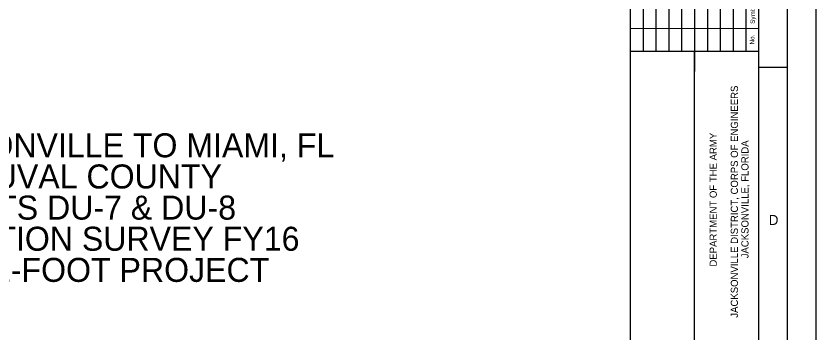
# Model space of a CAD drawing. Extents: x 464090 to 640095, y 2137521 to 2273520.
# Drawn here: x 584083 to 640089, y 2208273 to 2230445 of the extents above; entities that cross this region are included whole.
import ezdxf

# ---------------------------------------------------------------- set-up
doc = ezdxf.new("R2010")
doc.units = 0
for name, color, linetype in [('G-ANNO-NPLT', 7, 'Continuous'), ('G-ANNO-TEXT-TTLB', 7, 'Continuous'), ('G-ANNO-TTLB', 7, 'Continuous'), ('V-ANNO-TEXT', 7, 'Continuous')]:
    doc.layers.add(name, color=color, linetype=linetype)

msp = doc.modelspace()

# ---------------------------------------------------------------- linework, layer by layer
at = {"layer": 'G-ANNO-NPLT'}
msp.add_lwpolyline([(464090, 2273520), (640089, 2273520), (640089, 2137521), (464090, 2137521)], close=True, dxfattribs=at)
at = {"layer": 'G-ANNO-TTLB'}
for p, q in [((627088, 2269520), (627088, 2141521)), ((627982, 2261506), (627982, 2227990)), ((628882, 2261506), (628882, 2227990)), ((629782, 2261506), (629782, 2227990)), ((630682, 2261506), (630682, 2227990)), ((631582, 2261506), (631582, 2227990)), ((632482, 2261506), (632482, 2227990)), ((633382, 2261506), (633382, 2227990)), ((634282, 2261506), (634282, 2227990)), ((635182, 2261506), (635182, 2227990)), ((627089, 2229584), (636089, 2229582)), ((627089, 2227990), (636089, 2227990)), ((631563, 2193607), (631589, 2227990)), ((631589, 2227990), (631588, 2226573)), ((638089, 2226848), (636089, 2226848))]:
    msp.add_line(p, q, dxfattribs=at)
for points in [[(466090, 2139521), (638089, 2139521), (638089, 2271520), (466090, 2271520)], [(636089, 2269520), (471090, 2269520), (471090, 2141521), (636089, 2141521)]]:
    msp.add_lwpolyline(points, close=True, dxfattribs=at)

# ---------------------------------------------------------------- texts
at = {"layer": 'G-ANNO-TEXT-TTLB'}
for s, height, p in [('Symbol', 320, (635813, 2229898)), ('No.', 320, (635773, 2228453)), ('JACKSONVILLE DISTRICT, CORPS OF ENGINEERS', 500, (634624, 2209342)), ('DEPARTMENT OF THE ARMY', 500, (633144, 2212918)), ('JACKSONVILLE, FLORIDA', 500, (635364, 2213496))]:
    msp.add_text(s, height=height, rotation=90, dxfattribs=at).set_placement(p)
at = {"layer": 'G-ANNO-TTLB'}
msp.add_text('D', height=700, dxfattribs=at).set_placement((636783, 2215829))
at = {"layer": 'V-ANNO-TEXT'}
for s, p in [('IWW- JACKSONVILLE TO MIAMI, FL', (568672, 2220560)), ('DUVAL COUNTY', (580902, 2218382)), ('CUTS DU-7 & DU-8', (579518, 2216204)), ('EXAMINATION SURVEY FY16', (572594, 2214026)), ('10 & 12-FOOT PROJECT', (575975, 2211848))]:
    msp.add_text(s, height=1680, dxfattribs=at).set_placement(p)

doc.saveas('drawing.dxf')
